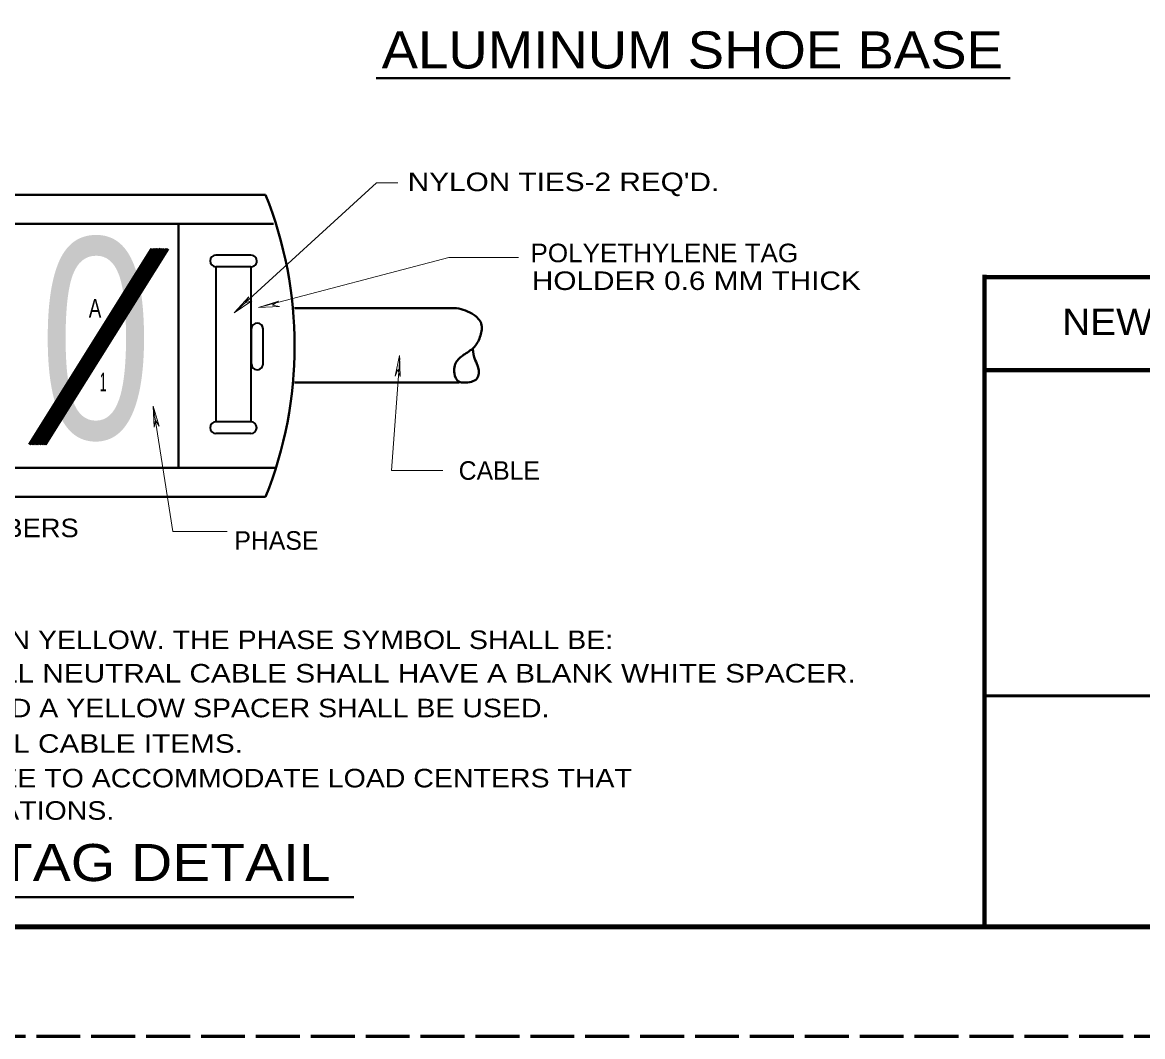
# Model space of a CAD drawing. Extents: x 312583 to 312854, y 144418 to 144597.
# Drawn here: x 312763.88 to 312809.8, y 144418.58 to 144460.17 of the extents above; entities that cross this region are included whole.
import ezdxf
from ezdxf.enums import TextEntityAlignment as Align

# ---------------------------------------------------------------- set-up
doc = ezdxf.new("R2010")
doc.units = 0
doc.header["$LTSCALE"] = 0.3
doc.linetypes.add('LONG_DASHED', pattern=[7.5, 6, -1.5])
doc.layers.add('1', color=7, linetype='Continuous', lineweight=35)
doc.layers.add('2', color=7, linetype='Continuous')

msp = doc.modelspace()

# ---------------------------------------------------------------- linework, layer by layer
at = {"layer": '1', "lineweight": 40}
for p, q in [((312778.3819, 144457.8763), (312804.3631, 144457.8763)), ((312733.3339, 144453.1015), (312773.8455, 144453.1015)), ((312770.2694, 144441.9004), (312770.2694, 144451.9121)), ((312764.1541, 144442.8612), (312769.1714, 144450.8903)), ((312764.1846, 144442.8612), (312769.2171, 144450.8903)), ((312764.238, 144442.8612), (312769.2705, 144450.8903)), ((312764.2761, 144442.8612), (312769.3162, 144450.8903)), ((312764.3219, 144442.8612), (312769.3544, 144450.8903)), ((312764.3829, 144442.8612), (312769.4001, 144450.8903)), ((312764.3905, 144442.8612), (312769.4154, 144450.8903)), ((312764.4286, 144442.8612), (312769.4382, 144450.8903)), ((312764.4591, 144442.8612), (312769.4764, 144450.8903)), ((312764.5125, 144442.8612), (312769.5374, 144450.8979)), ((312764.5582, 144442.8612), (312769.5831, 144450.8903)), ((312764.5964, 144442.8612), (312769.6212, 144450.8903)), ((312764.6421, 144442.8612), (312769.6746, 144450.8903)), ((312764.6802, 144442.8612), (312769.7051, 144450.8903)), ((312764.7412, 144442.8612), (312769.7661, 144450.8903)), ((312764.7794, 144442.8612), (312769.8042, 144450.8903)), ((312764.8175, 144442.8612), (312769.85, 144450.8903)), ((312775.0274, 144448.4579), (312781.6764, 144448.4579)), ((312775.0274, 144445.4079), (312781.7831, 144445.4079)), ((312733.3339, 144440.7109), (312773.8455, 144440.7109)), ((312734.3811, 144424.3068), (312777.466, 144424.3068))]:
    msp.add_line(p, q, dxfattribs=at)
at = {"layer": '1', "lineweight": 13}
for p, q in [((312778.3976, 144453.5972), (312772.5569, 144448.2597)), ((312778.3976, 144453.5972), (312779.2669, 144453.5972)), ((312781.3561, 144450.5319), (312773.5558, 144448.4732)), ((312781.3561, 144450.5319), (312784.2079, 144450.5319)), ((312772.5569, 144448.2597), (312773.1516, 144448.9154)), ((312773.1516, 144448.9154), (312773.0068, 144448.6638)), ((312772.5569, 144448.2597), (312773.2812, 144448.7477)), ((312773.2812, 144448.7477), (312773.0068, 144448.6638)), ((312773.5558, 144448.4732), (312774.3792, 144448.7324)), ((312773.5558, 144448.4732), (312774.4174, 144448.5189)), ((312774.3792, 144448.7324), (312774.1276, 144448.5799)), ((312774.4174, 144448.5189), (312774.1276, 144448.5799)), ((312779.3279, 144446.5135), (312779.1601, 144445.6595)), ((312779.3279, 144446.5135), (312779.3584, 144445.6519)), ((312779.0076, 144441.8013), (312779.3431, 144446.4221)), ((312779.1601, 144445.6595), (312779.2669, 144445.9341)), ((312779.3584, 144445.6519), (312779.2669, 144445.9341)), ((312770.0406, 144439.2927), (312769.2324, 144444.4395)), ((312769.24, 144444.4395), (312769.2705, 144443.5703)), ((312769.24, 144444.4395), (312769.4764, 144443.6084)), ((312769.2705, 144443.5703), (312769.3315, 144443.8601)), ((312769.4764, 144443.6084), (312769.3315, 144443.8601)), ((312779.0076, 144441.8013), (312781.1045, 144441.8013)), ((312770.0406, 144439.2927), (312772.2671, 144439.2927))]:
    msp.add_line(p, q, dxfattribs=at)
at = {"layer": '1'}
for p, q in [((312773.2431, 144450.6234), (312771.8096, 144450.6234)), ((312773.2431, 144450.1507), (312771.8096, 144450.1507)), ((312773.266, 144446.1704), (312773.266, 144447.6039)), ((312773.7388, 144446.1704), (312773.7388, 144447.6039)), ((312773.2431, 144443.7914), (312771.8096, 144443.7914)), ((312773.2431, 144443.3111), (312771.8096, 144443.3111))]:
    msp.add_line(p, q, dxfattribs=at)
at = {"layer": '1', "lineweight": 80}
for p, q in [((312803.31, 144423.1446), (312803.31, 144449.8146)), ((312803.31, 144449.7246), (312849, 144449.7246)), ((312803.31, 144445.9146), (312849, 144445.9146))]:
    msp.add_line(p, q, dxfattribs=at)
at = {"layer": '1', "lineweight": 53}
msp.add_line((312849, 144432.5546), (312803.2881, 144432.5546), dxfattribs=at)
at = {"layer": '1', "lineweight": 158}
msp.add_line((312616.5, 144423.0846), (312849, 144423.0846), dxfattribs=at)
at = {"layer": '1', "linetype": 'LONG_DASHED', "lineweight": 60}
msp.add_line((312851.75, 144418.5846), (312583.526, 144418.5846), dxfattribs=at)
at = {"layer": '1', "lineweight": 158}
msp.add_lwpolyline([(312849, 144423.0846), (312849, 144585.0846), (312616.5, 144585.0846), (312616.5, 144423.0846)], close=True, dxfattribs=at)
msp.add_lwpolyline([(312616.5, 144585.0846), (312616.5, 144423.0846), (312849, 144423.0846)], dxfattribs=at)
at = {"layer": '1', "lineweight": 40}
for points in [[(312732.8001, 144451.9121), (312756.9256, 144451.9121), (312774.1734, 144451.9121)], [(312732.8535, 144441.9004), (312756.9256, 144441.9004), (312774.2268, 144441.9004)]]:
    msp.add_lwpolyline(points, dxfattribs=at)
at = {"layer": '1'}
for points in [[(312771.8096, 144450.1507), (312771.8096, 144445.2707), (312771.8096, 144443.7914)], [(312773.2431, 144450.1507), (312773.2431, 144445.2707), (312773.2431, 144443.7914)]]:
    msp.add_lwpolyline(points, dxfattribs=at)
at = {"layer": '1', "lineweight": 40}
msp.add_arc((312758.3066, 144446.9062), 16.7284, 338.26294, 21.73706, dxfattribs=at)
at = {"layer": '1'}
for centre, radius, start, end in [((312771.8096, 144450.387), 0.2364, 89.98534, 268.16657), ((312773.2512, 144450.3871), 0.2364, 269.8984, 91.94969), ((312773.5023, 144447.604), 0.2364, 359.98534, 178.16657), ((312773.5024, 144446.1624), 0.2364, 179.8984, 1.94969), ((312771.8132, 144443.5512), 0.2402, 90.85072, 269.14928), ((312773.2393, 144443.5512), 0.2402, 270.90938, 89.09062)]:
    msp.add_arc(centre, radius, start, end, dxfattribs=at)
at = {"layer": '1', "lineweight": 40}
msp.add_spline([(312781.6764, 144448.4579), (312782.3779, 144448.1834), (312782.6829, 144447.8174), (312782.6524, 144447.3294), (312782.4084, 144446.8719), (312782.0119, 144446.5669), (312781.6764, 144446.2619), (312781.5849, 144445.7739), (312781.7679, 144445.4384), (312781.9966, 144445.4003), (312782.4999, 144445.5604), (312782.5609, 144446.0179), (312782.4389, 144446.3229), (312782.3321, 144446.7957)], degree=3, dxfattribs=at)

# ---------------------------------------------------------------- texts
at = {"layer": '1'}
for s, height, width, p in [('ALUMINUM SHOE BASE', 1.52, 1.1, (312791.3353, 144458.2809)), ('0', 8.235, 0.75, (312766.8876, 144443.0975)), ('A', 0.7625, 0.75, (312766.8534, 144448.0691)), ('NEW JERSEY DEPARTMENT OF TRANSPORTATION', 1.08, 1.1, (312826.2285, 144447.3546)), ('1', 0.7625, 0.5, (312767.185, 144445.0419)), ('CABLE IDENTIFICATION TAG DETAIL', 1.52, 1.15, (312755.9257, 144424.9611))]:
    msp.add_text(s, height=height, dxfattribs=dict(at, width=width)).set_placement(p, align=Align.CENTER)
for s, width, p in [("NYLON TIES-2 REQ'D.", 1.2, (312779.671, 144453.2504)), ('POLYETHYLENE TAG', 1.05, (312784.7035, 144450.3362)), ('HOLDER 0.6 MM THICK', 1.2, (312784.7591, 144449.198)), ('CIRCUIT NUMBERS', 1.1, (312755.7482, 144439.0616))]:
    msp.add_text(s, height=0.76, dxfattribs=dict(at, width=width)).set_placement(p)
for s, p in [('CABLE', (312781.7602, 144441.415)), ('PHASE', (312772.5645, 144438.5479))]:
    msp.add_text(s, height=0.76, dxfattribs=at).set_placement(p)
at = {"layer": '2'}
for s, width, p in [('TAG LETTERS SHALL BE BLACK ON YELLOW. THE PHASE SYMBOL SHALL BE:', 1.15, (312744.0546, 144434.4755)), ('A=RED,  B=BROWN,  C=BLUE.  ALL NEUTRAL CABLE SHALL HAVE A BLANK WHITE SPACER.', 1.2, (312744.0546, 144433.103)), ('WHEN A LETTER IS NOT REQUIRED A YELLOW SPACER SHALL BE USED.', 1.15, (312744.047, 144431.6771)), ('TAGS SHALL BE INCLUDED IN ALL CABLE ITEMS.', 1.2, (312744.047, 144430.2207)), ('TAG SHALL BE OF SUFFICIENT SIZE TO ACCOMMODATE LOAD CENTERS THAT', 1.15, (312744.0546, 144428.8025)), ('HAVE MULTIPLE LETTER DESIGNATIONS.', 1.15, (312744.1309, 144427.4757))]:
    msp.add_text(s, height=0.76, dxfattribs=dict(at, width=width)).set_placement(p)

doc.saveas('drawing.dxf')
